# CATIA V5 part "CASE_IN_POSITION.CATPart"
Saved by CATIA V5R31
Part number: CASE
Revision: 01
Nomenclature: CASE
Source: Unknown
Property "部品番号(B社)": "MOLD222222"
Property "部品名称(B社)": "CASE"
Property "Version(B社)": "01"
Property "材質(B社)": "POM"
Bounding box of the stored display mesh (mm): x -11.5 to 11.5, y -19.4 to 19.4, z -29.2 to 11
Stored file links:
  \\solize.local\damia\dept\DDE_Design\10_order\2305701_JAMA_変換検証STEP3_お手本モデル作成\work\03_東洋電装_スイッチ\10_CATIA_V5\CASE_IN_POSITION.CATPart
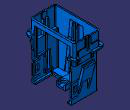
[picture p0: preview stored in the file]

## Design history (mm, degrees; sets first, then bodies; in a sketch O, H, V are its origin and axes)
WSupportSet1
AxisSystem1: origin (0, 0, 0), X (1, 0, 0), Y (0, 1, 0), Z (0, 0, 1)
Set1
  Plane1: type Offset, RefPlane face of Solid1, Offset 0, reversed
  Plane2: type Offset, RefPlane face of Solid1, Offset 0, reversed
  Sketch1 "P1" on YZ plane of AxisSystem1, origin (0, 0, 0), H (0, 1, 0), V (0, 0, 1)
    axis line L1 (-15.75, -3.8027) -> (-15.75, -6.1282)
    point P3 (-15.4517, -14.6627)
    point P4 (-14.75, -24.4178)
    point P5 (-14.75, -24.4178)
    point P6 (-15.7825, -6.2046)
    point P7 (-15.7825, -6.2046)
    point P8 (-15.815, -4.9717)
    point P9 (-15.815, -4.9717)
    point P10 (-15.75, -4.3076)
    point P12 (-16.4468, -4.2395)
    point P13 (-16.4469, -4.2396)
    point P14 (-16.8778, -5.0515)
    point P15 (-16.8778, -5.0515)
    point P16 (-17.5879, -5.6352)
    point P17 (-14.75, -14.649)
    line L2 (-15.4517, -14.6627) -> (-15.7825, -6.2046)
    line L3 (-16.8778, -5.0515) -> (-17.5879, -5.6352)
    line L4 (-16.4468, -4.2395) -> (-16.8778, -5.0515)
    line L5 (-15.75, -4.3076) -> (-16.4469, -4.2396)
    line L6 (-15.815, -4.9717) -> (-15.7501, -4.3076)
    arc A1 centre (-10.8332, -5.4575) radius 5.0054 from (-15.815, -4.9717) to (-15.7825, -6.2046) ccw
    arc A2 centre (-15.101, -14.649) radius 0.351 from (-15.4517, -14.6627) to (-14.75, -14.649) ccw
    line L7 (-14.75, -14.649) -> (-14.75, -24.4178)
    reference projected line E1 (-14.75, -5) -> (-14.75, 0) from edge [face of Solid1 | face of Solid1]
    line L8 (-17.5879, -5.6352) -> (-16.9461, -13.9476)
    line L9 (-14.75, -24.4178) -> (-16.1224, -18.9821)
    arc A3 centre (12.9649, -11.6383) radius 30 from (-16.1224, -18.9821) to (-16.9461, -13.9476) cw
    distance L1 E1 = 1
    radius A3 = 30
    fix: P3, P4, P5, P6, P7, P8, P9, P12, P13, P14, P15, P16, P17, L2, L3, L4, L5, L6, A1, A2, L7, L8, L9, A3
    coincidence: P10 L1
    tangency: A3 L9, A3 L8
  Sketch2 "P2" on YZ plane of AxisSystem1, origin (0, 0, 0), H (0, 1, 0), V (0, 0, 1)
    point P1 (-15.4413, -14.7351)
    point P2 (-15.4413, -14.7351)
    point P3 (-14.75, -24.4178)
    point P4 (-14.9439, -4.9435)
    point P5 (-14.9439, -4.9435)
    point P6 (-14.8494, -4.283)
    point P7 (-14.8494, -4.283)
    point P8 (-15.5423, -4.1838)
    point P9 (-15.5423, -4.1838)
    point P10 (-16.0092, -4.9757)
    point P11 (-16.0092, -4.9757)
    point P12 (-16.7974, -5.5666)
    point P13 (-14.75, -14.649)
    point P14 (-15.4154, -5.7678)
    point P15 (-15.4154, -5.7678)
    line L1 (-15.4413, -14.7351) -> (-15.4154, -5.7678)
    line L2 (-16.0092, -4.9757) -> (-16.7974, -5.5666)
    line L3 (-15.5423, -4.1838) -> (-16.0092, -4.9757)
    line L4 (-14.8494, -4.283) -> (-15.5423, -4.1838)
    line L5 (-14.9439, -4.9435) -> (-14.8494, -4.283)
    arc A1 centre (-10.8544, -7.8298) radius 5.0054 from (-14.9439, -4.9435) to (-15.4154, -5.7678) ccw
    arc A2 centre (-15.101, -14.649) radius 0.351 from (-15.4413, -14.7351) to (-14.75, -14.649) ccw
    line L6 (-14.75, -14.649) -> (-14.75, -24.4178)
    construction line L7 (-14.75, -14.649) -> (-14.75, -4.5)
    axis line L8 (-14.85, -3.8027) -> (-14.85, -6.1282)
    point P19 (-14.75, -24.4178)
    line L9 (-16.7974, -5.5666) -> (-16.8004, -13.1793)
    line L10 (-16.0398, -19.309) -> (-14.75, -24.4178)
    arc A3 centre (8.1995, -13.1892) radius 25 from (-16.0398, -19.309) to (-16.8004, -13.1793) cw
    point P20 (-16.0398, -19.309)
    point P21 (-16.8004, -13.1793)
    distance L8 L7 = 0.1
    radius A3 = 25
    coincidence: P2 P1, P10 P11, P8 P9, P6 P7, P4 P5, P14 P15, P19 P3
    vertical: L7 V
    fix: L7, P19, A2, L6, P21, P20, P3, P13, P12, P15, P14, P5, P4, P7, P6, P9, P8, P11, P10, P1, P2, A3, L10, L9, A1, L5, L4, L3, L2, L1
    tangency: A3 L10, A3 L9
Set2 "Position"
  MultiSel1
Body1 (main body)
  Solid1: solid without history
